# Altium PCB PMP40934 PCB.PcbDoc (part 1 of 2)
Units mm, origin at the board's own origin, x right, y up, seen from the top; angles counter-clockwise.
Board outline 30.1 x 65.43 mm, 4 copper layers (Component Side, Signal Layer 1, Signal Layer 2, Solder Side), stack 0.921 mm thick; 71 components, 34 nets, 202 pads, 421 vias.
Unrouted connection lines stored in the file: 46.
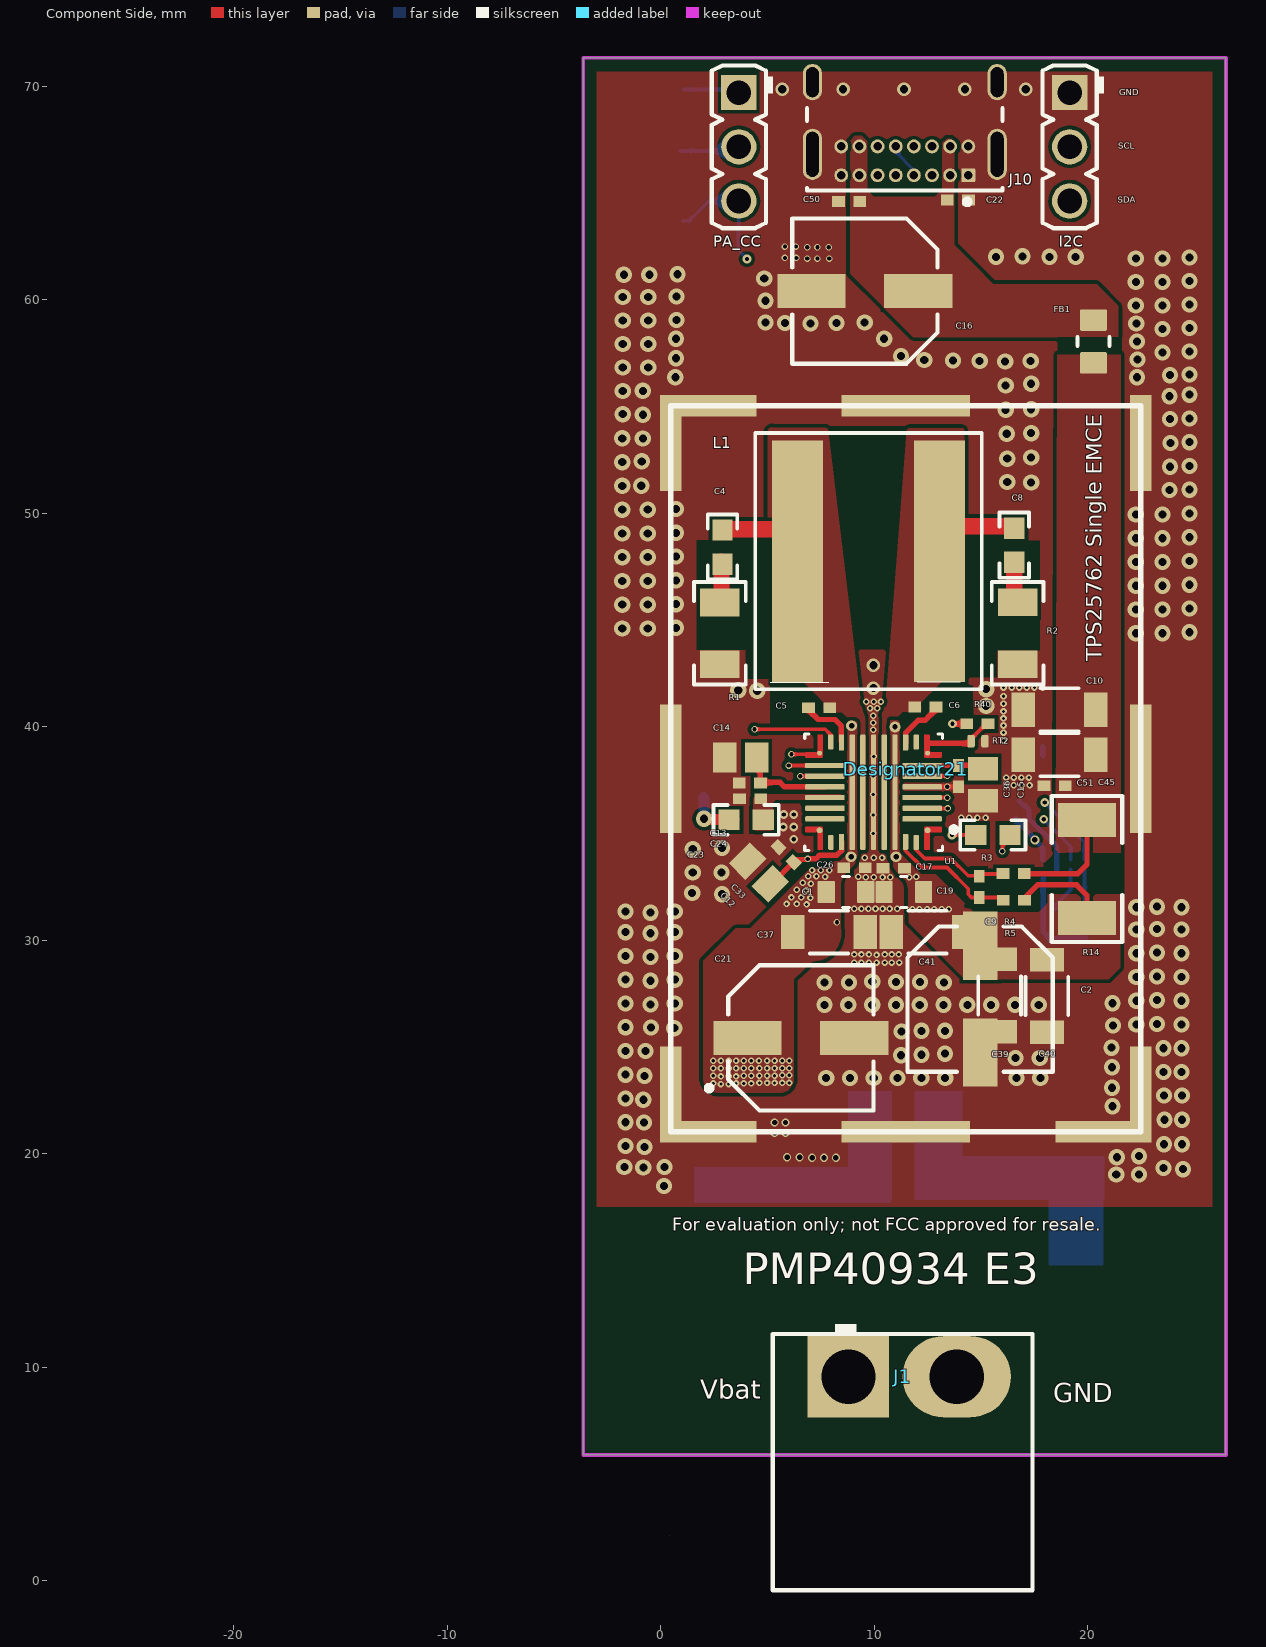
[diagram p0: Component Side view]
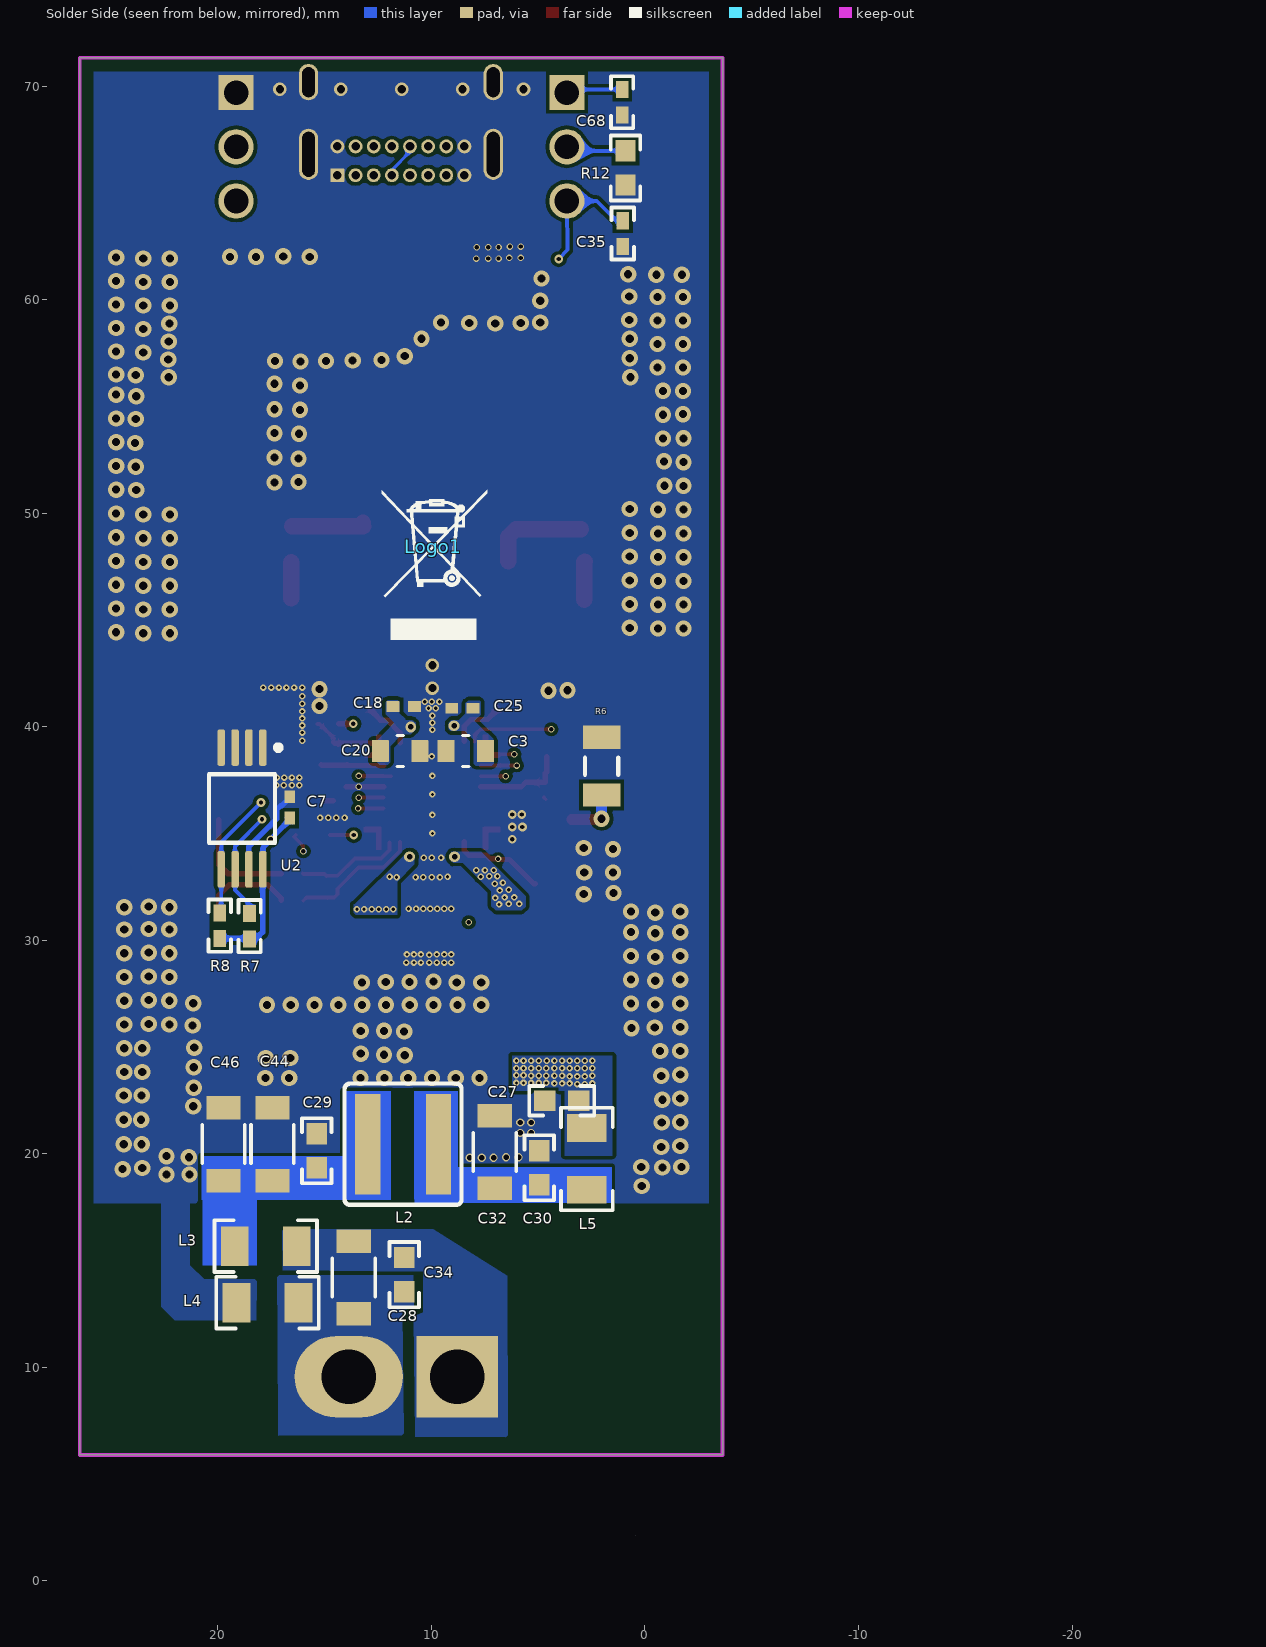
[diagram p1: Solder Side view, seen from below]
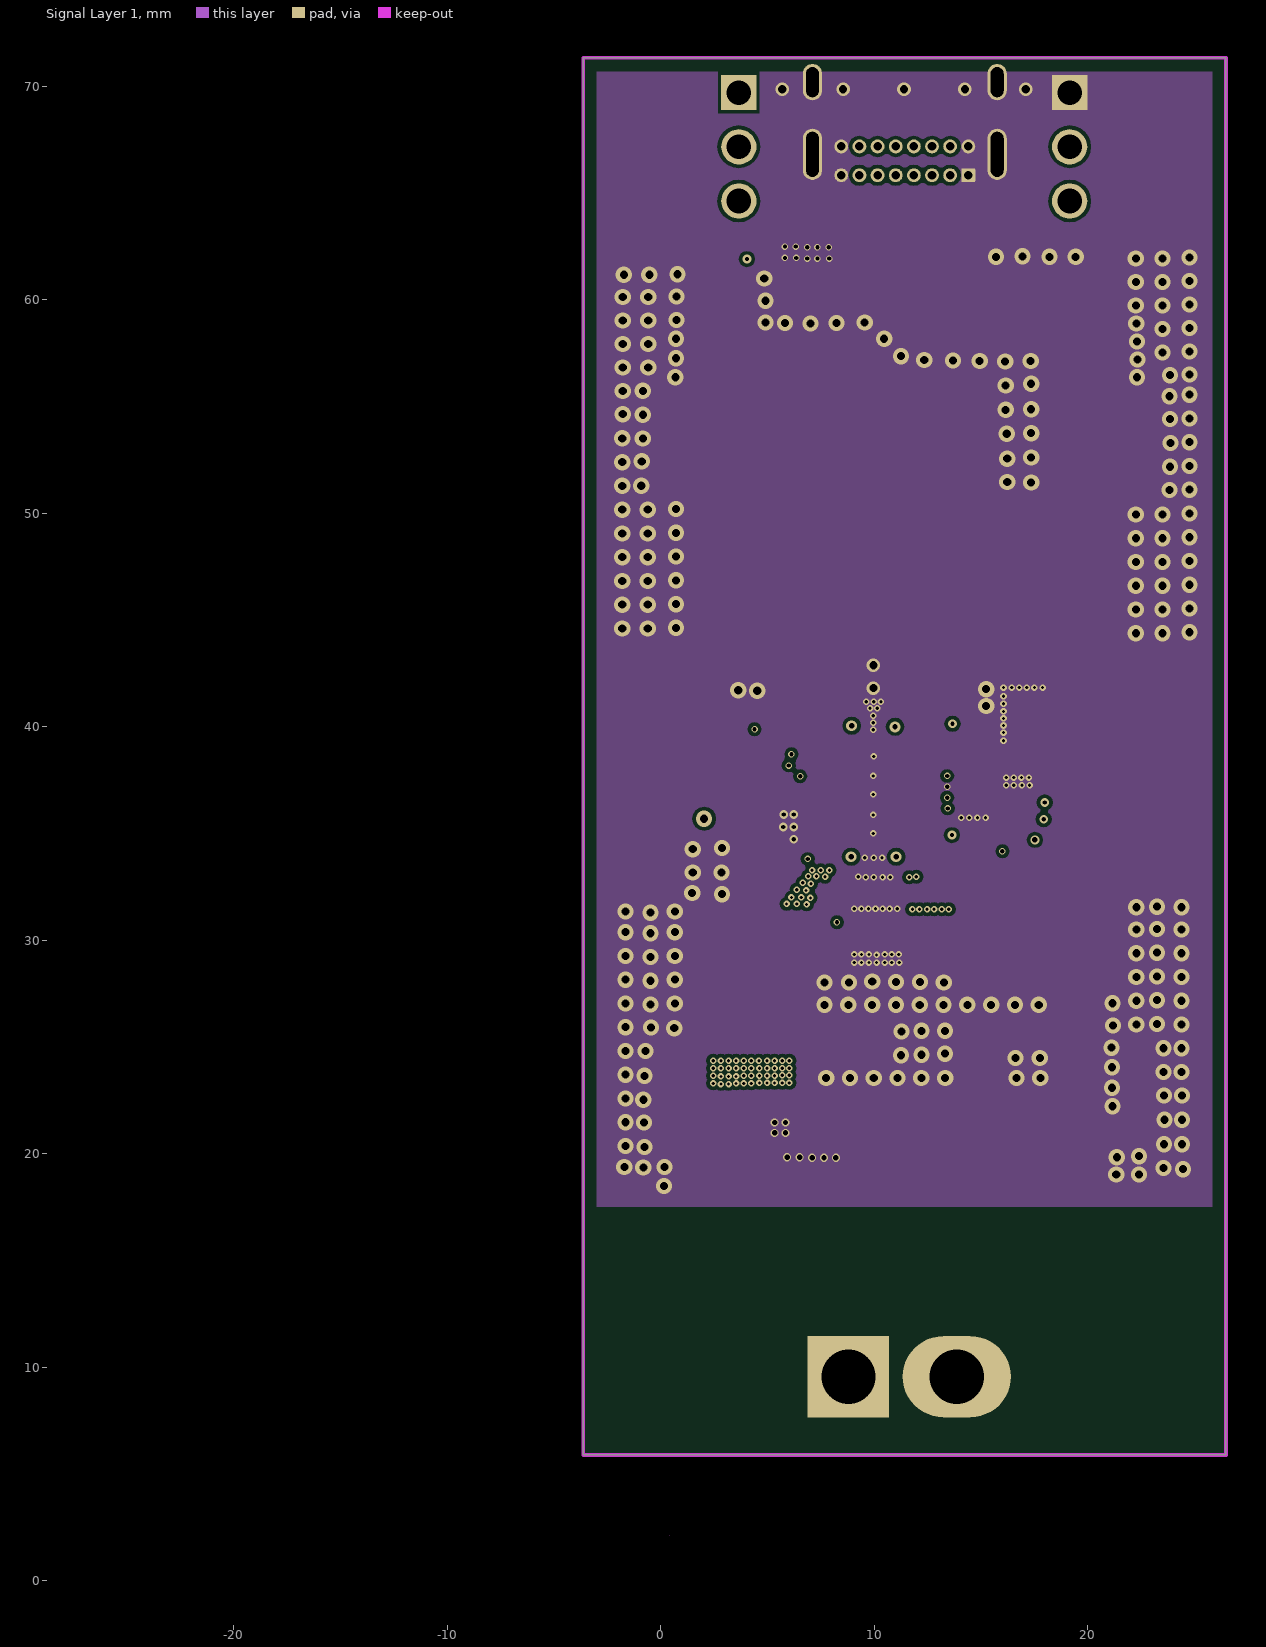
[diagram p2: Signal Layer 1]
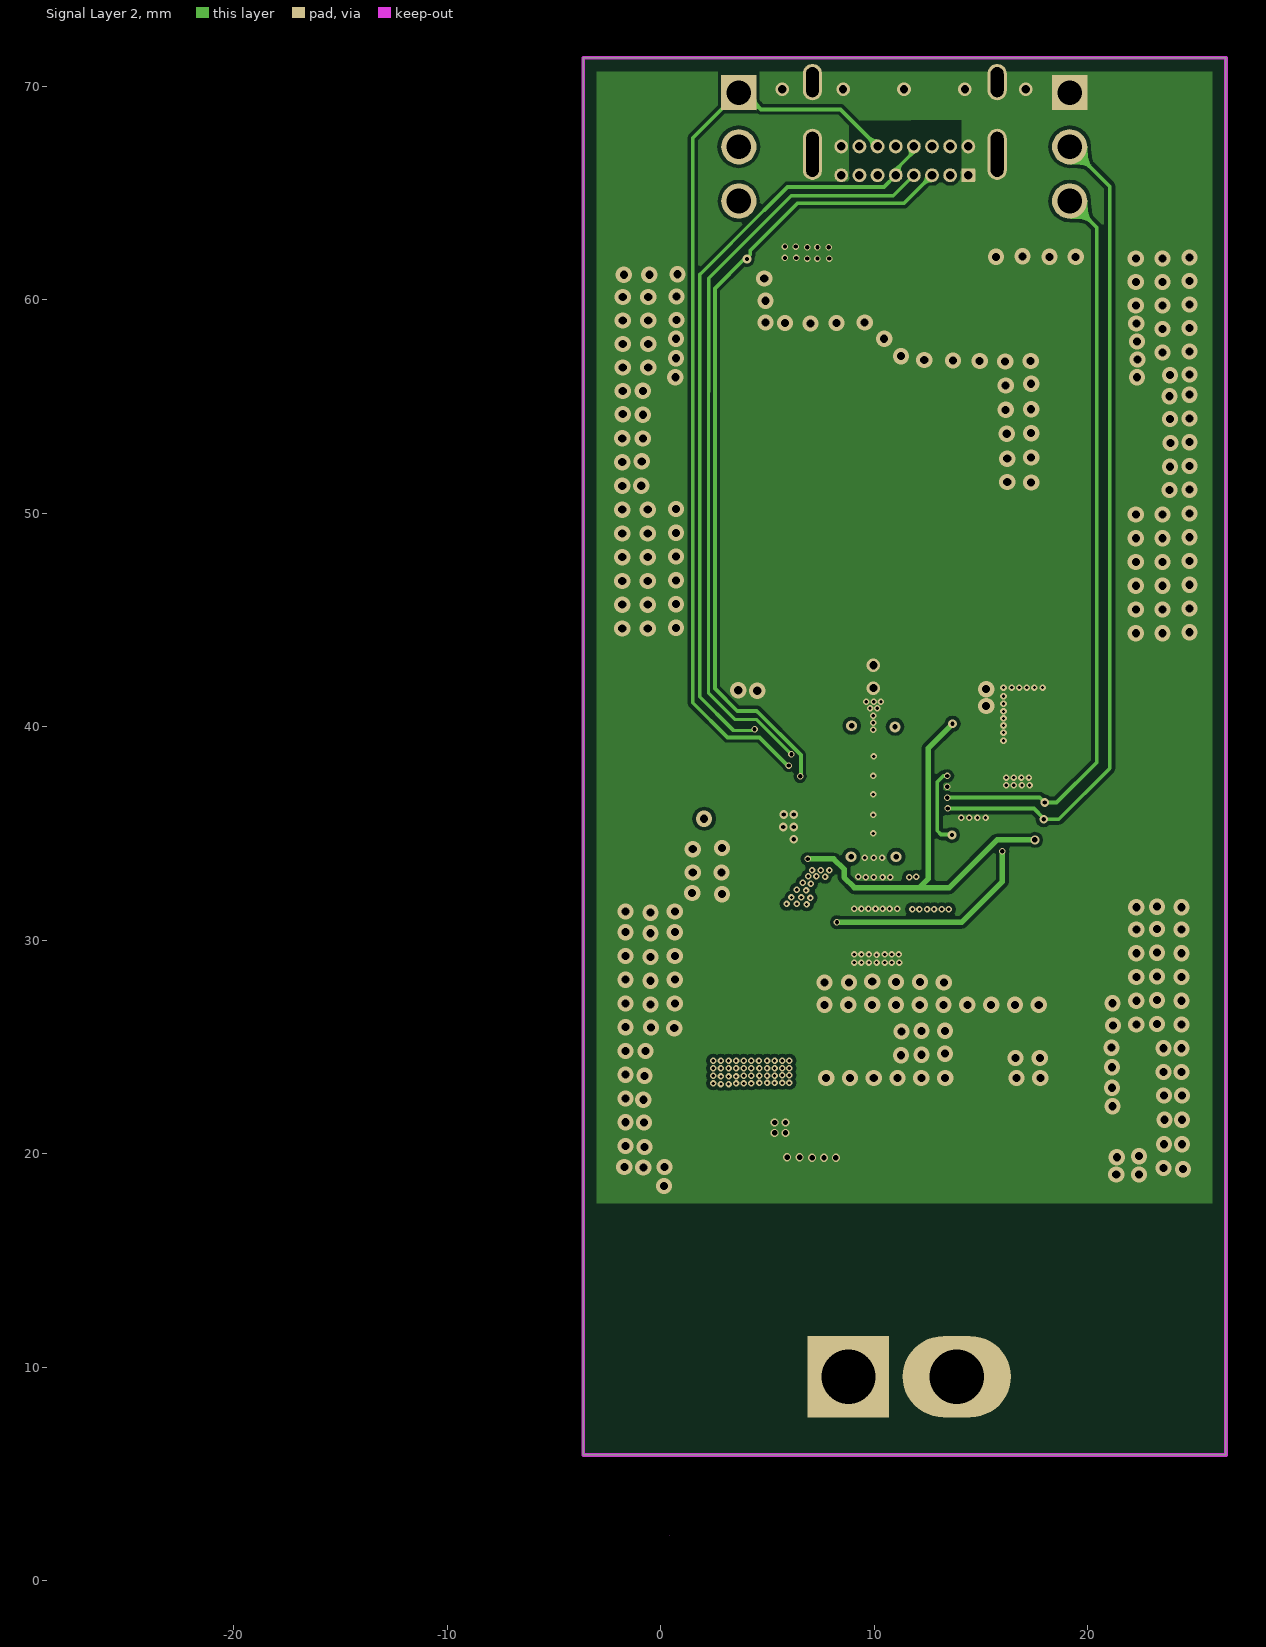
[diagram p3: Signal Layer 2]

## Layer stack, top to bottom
Top Solder: solder mask 0.0102, Solder Resist, Dk 3.5
Component Side: signal copper 0.072
Dielectric 1: core 0.254, FR-4, Dk 4.8
Signal Layer 1: signal copper 0.0711
Dielectric 3: prepreg 0.127, Dk 4.2
Signal Layer 2: signal copper 0.0711
Dielectric 4: core 0.254, FR-4, Dk 4.8
Solder Side: signal copper 0.072
Bottom Solder: solder mask 0.0102, Solder Resist, Dk 3.5

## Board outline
-3.632,5.893 -3.632,71.323 26.467,71.323 26.467,5.893
cut-out: 0.432,2.134

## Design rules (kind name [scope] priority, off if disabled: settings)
AcuteAngle [All] p1: minimum=4.50000000000000E+0001 checktracksonly=FALSE
AssemblyTestPointUsage [All] p1: valid=2
BoardOutlineClearance BoardOutlineClearance_MountingHoles [OnCopper and InComponentClass('Mounting Holes')] p1: gap=0.254 ignorepadtopadclearanceinfootprint=FALSE
BoardOutlineClearance BoardOutlineClearance_Poly [OnCopper and IsPoly] p2: gap=0.635 ignorepadtopadclearanceinfootprint=FALSE
BoardOutlineClearance [OnCopper and Not InComponentClass('Logo') and not InComponentClass('FiducialMark') and not InRegion(1000,500,4000,800) and not InPoly] p3: gap=0.254 ignorepadtopadclearanceinfootprint=FALSE
Clearance Clearance_Keepouts [((IsTrack Or IsArc) And Not InPoly) And IsFree and IsKeepOut vs ((IsTrack Or IsArc) And Not InPoly) And IsFree and IsKeepOut] p1: gap=0 ignorepadtopadclearanceinfootprint=FALSE
Clearance Clearance_Poly [InPolygon] p2: gap=0.165 ignorepadtopadclearanceinfootprint=FALSE except(0: Arc-Hole Track-Hole SMDPad-Hole THPad-Hole Via-Hole Fill-Hole Poly-Hole Region-Hole Text-Hole)
Clearance Clearance_FiducialMark [IsKeepOut and InComponentClass('FiducialMark') vs IsPad and InComponentClass('FiducialMark')] p3: gap=0 ignorepadtopadclearanceinfootprint=FALSE
Clearance [All] p4: gap=0 ignorepadtopadclearanceinfootprint=FALSE
ComponentClearance ComponentClearance_MountingHoles_FiducialMarks [InComponentClass('Mounting Holes') vs InComponentClass('FiducialMark')] p1: gap=0.127 collisioncheckmode=3 verticalgap=0.076 showdistances=FALSE
ComponentClearance ComponentClearance_Shunt [InComponentClass('Header') vs InComponentClass('Shunt')] p2: gap=0 collisioncheckmode=3 verticalgap=0 showdistances=FALSE
ComponentClearance ComponentClearance_Logo [InComponentClass('Logo')] p3: gap=1.27 collisioncheckmode=3 verticalgap=0.254 showdistances=FALSE
ComponentClearance ComponentClearance_ScrewToNut [(HasFootprint('NY PMS 440 0025 PH')) vs (HasFootprint('Keystone_1902C'))] p4: gap=0.127 collisioncheckmode=3 verticalgap=0.254 showdistances=FALSE
ComponentClearance ComponentClearance_MountingHoles [InComponentClass('Mounting Holes')] p5: gap=1.27 collisioncheckmode=3 verticalgap=2540 showdistances=FALSE
ComponentClearance ComponentClearance_SmallPassives [HasFootprint('0201*') or HasFootprint('0402*') or HasFootprint('0508') or HasFootprint('0603*') or HasFootprint('0612') or HasFootprint('0805*') or HasFootprint('0815*') or HasFootprint('0830*') or HasFootprint('1206*') or HasFootprint('1210*') or HasFootprint('1808*') or HasFootprint('1812*') or HasFootprint('1825*') or HasFootprint('2010*') or HasFootprint('2220*') or HasFootprint('2225*') or HasFootprint('2512*') or HasFootprint('2728*') or HasFootprint('3518*') vs HasFootprint('0201*') or HasFootprint('0402*') or HasFootprint('0508') or HasFootprint('0603*') or HasFootprint('0612') or HasFootprint('0805*') or HasFootprint('0815*') or HasFootprint('0830*') or HasFootprint('1206*') or HasFootprint('1210*') or HasFootprint('1808*') or HasFootprint('1812*') or HasFootprint('1825*') or HasFootprint('2010*') or HasFootprint('2220*') or HasFootprint('2225*') or HasFootprint('2512*') or HasFootprint('2728*') or HasFootprint('3518*')] p6: gap=0 collisioncheckmode=3 verticalgap=0 showdistances=FALSE
ComponentClearance ComponentClearance_THtoSMT [IsThruComponent vs IsSMTComponent] p7: gap=0.127 collisioncheckmode=3 verticalgap=0.127 showdistances=FALSE
ComponentClearance ComponentClearance_THtoTH [IsThruComponent vs IsThruComponent] p8: gap=0.127 collisioncheckmode=3 verticalgap=0.127 showdistances=FALSE
ComponentClearance [All] p9: gap=0 collisioncheckmode=3 verticalgap=0 showdistances=FALSE
DiffPairsRouting [All] p1: maxlimit=2.54 minlimit=0.152 mostfreqgap=0.254 toplayer_minwidth=0.152 toplayer_maxwidth=0.381 toplayer_prefwidth=0.381 midlayer1_minwidth=0.152 midlayer1_maxwidth=0.381 midlayer1_prefwidth=0.381 midlayer2_minwidth=0.152 midlayer2_maxwidth=0.381 midlayer2_prefwidth=0.381 bottomlayer_minwidth=0.152 bottomlayer_maxwidth=0.381 bottomlayer_prefwidth=0.381 maxuncoupledlength=25.4
FabricationTestPointUsage TestPointUsage [All] p1: valid=2 allowmultiple=FALSE
FabricationTestpoint Testpoint [All] p1: side=3 testpointundercomponent=TRUE minsize=1.016 maxsize=2.54 preferedsize=1.524 minholesize=0 maxholesize=1.016 preferedholesize=0.813 testpointgrid=0.025 allowsidetop=TRUE allowsidebottom=TRUE usegrid=TRUE gridtolerance=0
FanoutControl Fanout_LCC [IsLCC] p1: bgadir=Out bgaviamode=Centered fanoutstyle=Auto fanoutdirection=Alternating viagrid=0.025 // Fanout_LCC (Default Rule)
FanoutControl Fanout_BGA [IsBGA] p2: bgadir=Out bgaviamode=Centered fanoutstyle=Auto fanoutdirection=Alternating viagrid=0.025 // Fanout_BGA (Default Rule)
FanoutControl Fanout_Default [All] p4: bgadir=Out bgaviamode=Centered fanoutstyle=Auto fanoutdirection=Alternating viagrid=0.025 // Fanout_Default (Default Rule)
FanoutControl Fanout_Small [(CompPinCount < 5)] p5: bgadir=Out bgaviamode=Centered fanoutstyle=Auto fanoutdirection=OutThenIn viagrid=0.025 // Fanout_Small (Default Rule)
HoleSize [All] p1: absolutevalues=TRUE maxlimit=7.62 minlimit=0.127 maxpercent=80.000 minpercent=20.000
HoleToHoleClearance [All] p1: gap=0 allowstackedmicrovias=TRUE
MinimumAnnularRing MinimumAnnularRing_ThermalPadVias [IsVia and InAnyComponent] p1: minimumring=0.038
MinimumAnnularRing [All] p2: minimumring=0.038
MinimumSolderMaskSliver MinimumSolderMaskSliver_Logo [InComponentClass('Logo') vs InComponentClass('Logo')] p1: minsoldermaskwidth=0.018
MinimumSolderMaskSliver [All] p2: minsoldermaskwidth=0
PlaneConnect [All] p1: planeconnectstyle=Direct reliefexpansion=0.254 reliefentries=4 reliefconductorwidth=0.254 reliefairgap=0.254
PolygonConnect [All] p1: connectstyle=Direct reliefconductorwidth=0.254 reliefentries=4 polygonreliefangle="90 Angle" airgapwidth=0.254
RoutingVias ThermalPadVias [IsVia and InAnyComponent] p1: holewidth=1.27 width=1.27 viastyle="Through Hole" minholewidth=0.127 minwidth=0.254 maxholewidth=2.54 maxwidth=5.08
RoutingVias [All] p2: holewidth=0.254 width=0.406 viastyle="Through Hole" minholewidth=0.152 minwidth=0.254 maxholewidth=1.27 maxwidth=1.778
ShortCircuit [All vs InNet('No Net')] p1: allowed=FALSE
SilkToBoardRegionClearance [Not ((IsComment or IsDesignator) And (Hide <> 'False')) and not InRegion(1000,500,4000,800)] p1:
SilkToSilkClearance SilkToSilkClearance_Pb-FreeLogo [(HasFootprint('Pb-Free_Overlay_Medium') OR HasFootprint('Pb-Free_Overlay_Small')) vs (HasFootprint('Pb-Free_Overlay_Medium') OR HasFootprint('Pb-Free_Overlay_Small'))] p1: silktosilkclearance=0
SilkToSilkClearance [All] p2: silktosilkclearance=0
SilkToSolderMaskClearance SilkToComponentPadClearance [(IsPad or IsFill or IsRegion) and InAnycomponent] p1: minsilkscreentomaskgap=0 clearancetoexposedcopper=TRUE
SilkToSolderMaskClearance "Silk to Solder Mask Opening" [All] p2: minsilkscreentomaskgap=0 clearancetoexposedcopper=FALSE
SolderMaskExpansion [All] p1: expansion=0.05
Width [All] p1: maxlimit=2.54 minlimit=0.152 preferedwidth=0.254 checkconnectedcopper=TRUE
13 further rules are at their usual default settings.

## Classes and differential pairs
component class TPS25762: 3 C1 C2 C3 C4 C5 C6 C7 C8 C9 C10 C12 C13 C14 C15 C16 C17 C18 C19 C20 C21 C22 C23 C24 C25 C26 C33 C35 C36 C37 C39 C40 C41 C45 C50 C51 C68 FB1 I2C J10 L1 PA_CC R1 R2 R3 R4 R5 R6 R7 R8 R12 R14 R40 RT2 U1 U2
component class "Input filter": C27 C28 C29 C30 C32 C34 C44 C46 J1 L2 L3 L4 L5
component class Hardware: !PCB1 Logo1 Logo3
component class Header: I2C PA_CC
differential pair PA_D: +PA_D_P -PA_D_N

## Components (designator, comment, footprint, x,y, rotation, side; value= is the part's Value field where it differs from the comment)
C1 "GRT21BC71H475KE13L" FP-CGA4J1X7R1H475K125AC_0805-MFG 8.676,32.258 r180 top value=4.7µF
C2 "EEHZK1V101XP" Panasonic_D 14.961,27.243 r270 top value=100uF
C3 "GRT21BC71H475KE13L" FP-CGA4J1X7R1H475K125AC_0805-MFG 8.393,38.862 r180 bottom value=4.7µF
C4 "GRM188R72A332KA01D" 0603 2.896,48.412 r270 top value=3300pF
C5 "GRT155R71H104KE01D" 0402L 7.417,40.894 r0 top value=0.1uF
C6 "GRT155R71H104KE01D" 0402L 12.395,40.919 r180 top value=0.1uF
C7 "GRT155R71H104KE01D" 0402L 16.637,36.22 r270 bottom value=0.1uF
C8 "GRM188R72A332KA01D" 0603 16.561,48.501 r270 top value=3300pF
C9 "CGA3E2X7R1H104K080AA" 0402L 14.91,32.495 r90 top value=0.22uF
C10 "GRT31CD71H106KE13L" 1206_190 18.667,40.792 r180 top value=10uF
C12 "GCM21BR71C475KA73K" 0805L 4.6,33.169 r135 top value=4.7uF
C13 "GRT155R71H104KE01D" 0402L 4.174,37.363 r180 top value=0.1uF
C14 "GCM21BR71C475KA73K" 0805L 3.746,38.557 r180 top value=4.7uF
C15 "GCM21BR71C475KA73K" 0805L 15.088,37.274 r270 top value=4.7uF
C16 "EEHZK1V101XP" Panasonic_D 9.565,60.401 r180 top value=100uF
C17 "GRT155R71H104KE01D" 0402L 10.914,33.376 r0 top value=0.1uF
C18 "GRT155R71H104KE01D" 0402L 11.295,40.945 r0 bottom value=0.1uF
C19 "GRT21BC71H475KE13L" FP-CGA4J1X7R1H475K125AC_0805-MFG 11.39,32.258 r0 top value=4.7µF
C20 "GRT21BC71H475KE13L" FP-CGA4J1X7R1H475K125AC_0805-MFG 11.466,38.862 r0 bottom value=4.7µF
C21 "EEHZK1V101XP" Panasonic_D 6.561,25.425 r0 top value=100uF
C22 "GRT155R71H104KE01D" 0402L 13.919,64.668 r180 top value=0.1uF
C23 "CGA3E3X7R1H474K080AE" 0603 4.001,35.636 r180 top value=0.47uF
C24 "GRT155R71H104KE01D" 0402L 4.183,36.627 r180 top value=0.1uF
C25 "GRT155R71H104KE01D" 0402L 8.552,40.869 r180 bottom value=0.1uF
C26 "GRT155R71H104KE01D" 0402L 9.076,33.401 r180 top value=0.1uF
C27 "GCM1887U2A392JA16D" 0603 3.899,22.479 r0 bottom value=3900pF
C28 "GRT31CD71H106KE13L" 1206_190 13.64,14.2 r270 bottom value=10uF
C29 "GCM1887U2A392JA16D" 0603 15.367,20.142 r90 bottom value=3900pF
C30 "GCM1887U2A392JA16D" 0603 4.953,19.342 r90 bottom value=3900pF
C32 "GRT31CD71H106KE13L" 1206_190 7.036,20.091 r90 bottom value=10uF
C33 "GRT155R71H104KE01D" 0402L 5.869,34.009 r135 top value=0.1uF
C34 "GCM1887U2A392JA16D" 0603 11.278,14.34 r270 bottom value=3900pF
C35 "GRM155R71H331KA01D" 0402 1.041,63.094 r270 bottom value=330pF
C36 "GRT155R71H104KE01D" 0402L 13.945,37.686 r270 top value=0.1uF
C37 "GRT31CD71H106KE13L" 1206_190 7.873,30.378 r0 top value=10uF
C39 "GRT31CD71H106KE13L" 1206_190 15.875,27.408 r270 top value=10uF
C40 "GRT31CD71H106KE13L" 1206_190 18.085,27.383 r270 top value=10uF
C41 "GRT31CD71H106KE13L" 1206_190 12.495,30.378 r180 top value=10uF
C44 "GRT31CD71H106KE13L" 1206_190 17.45,20.447 r90 bottom value=10uF
C45 "GRT31CD71H106KE13L" 1206_190 18.671,38.684 r180 top value=10uF
C46 "GRT31CD71H106KE13L" 1206_190 19.736,20.447 r90 bottom value=10uF
C50 "GRT155R71H104KE01D" 0402L 8.822,64.592 r0 top value=0.1uF
C51 "GRT155R71H104KE01D" 0402L 18.448,37.236 r0 top value=0.1uF
C68 "GRM155R71H331KA01D" 0402 1.067,69.24 r270 bottom value=330pF
Designator21 "Comment" "Shield 19.7mm X 19.7mm" 0.476,21.031 r0 top
FB1 "BLM21SP700SZ1D" 0805_HV1 20.269,58.039 r90 top
I2C "61300311121" WURTH_61300311121 19.152,67.158 r270 top
J1 "1757242" PHOENIX_1757242 11.328,5.563 r0 top
J10 "USB4085-GF-A" FP-USB4085-GF-A_PTH_USB-C-MFG 11.43,69.85 r180 top
L1 "XAL1010-472MEB" XAL1010 9.728,47.752 r0 top value=4.7uH
L2 "XFL5030-472MEC" XFL5030 11.328,20.447 r180 bottom value=4.7uH
L3 "BLM31SN500SZ1L" 1206 17.757,15.672 r0 bottom value="50 ohm"
L4 "BLM31SN500SZ1L" 1206 17.681,13.03 r0 bottom value="50 ohm"
L5 "BLM31SN500SZ1L" 1206 2.718,19.759 r90 bottom value="50 ohm"
Logo1 "WEEE logo" WEEE_Minimum 9.906,48.438 r180 bottom
Logo3 "FCC disclaimer" FCC_disclaimer 32.233,20.828 r90 top
PA_CC "61300311121" WURTH_61300311121 3.658,67.158 r270 top
R1 "ERJ-8RQF2R2V" 1206 2.769,44.372 r90 top value=2.20
R2 "CRCW12061R00FKEA" 1206 16.713,44.376 r90 top value=1.00
R3 "CRCW060347K0FKEA" 0603 15.554,34.925 r0 top value=47.0k
R4 "RMCF0603ZT0R00" 0402L 16.527,33.122 r0 top value=0
R5 "RMCF0603ZT0R00" 0402L 16.543,31.877 r0 top value=10.0
R6 "RC1206FR-0710RL" 1206L 2.032,38.151 r270 bottom value=10.0
R7 "RK73H1ETTP3301F" 0402 18.517,30.658 r270 bottom value=3.30k
R8 "RK73H1ETTP3301F" 0402 19.914,30.683 r270 bottom value=3.30k
R12 "CRCW06035K10JNEA" 0603 0.914,66.167 r90 bottom value=5.1k
R14 "WSL2010R0100FEA18" 2010 19.964,33.336 r270 top value=0.01
R40 "ERJ-2GEJ103X" 0402L 14.834,40.132 r180 top value=10k
RT2 "TMP6131DECR" DEC0002A 14.859,39.319 r180 top
U1 "TPS25772RQLRQ1" RQL0029A-MFG 9.968,36.932 r180 top
U2 "24LC256-I/ST" TSSOP-8 18.872,36.17 r270 bottom

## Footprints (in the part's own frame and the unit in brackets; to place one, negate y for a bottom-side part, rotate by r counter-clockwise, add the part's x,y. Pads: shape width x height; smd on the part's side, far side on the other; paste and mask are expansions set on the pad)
0402 [mm] "0402 from SM-752 data"
  rect 0.8x0.6 smd: 1(-0.6,0) 2(0.6,0)
  silkscreen extent -1.22,-0.52 1.22,0.52, body extent -0.55,-0.3 0.55,0.3, height 0.6
0402L [mm] "0402 from SM-752 data"
  rect 0.6x0.5 smd: 1(-0.5,0) 2(0.5,0)
  body extent -0.55,-0.3 0.55,0.3, height 0.6
0603 [mm] "0603 from SM-752 data"
  rect 1x0.95 smd: 1(-0.8,0) 2(0.8,0)
  silkscreen extent -1.52,-0.69 1.52,0.69, body extent -0.87,-0.47 0.87,0.47, height 1
0805_HV1 [mm]
  rrect10% 1x1.25 smd: 1(-1,0) 2(1,0)
  silkscreen extent -0.2,-0.75 0.2,0.75, body extent -1.35,-0.82 1.35,0.82, height 0.25
0805L [mm] "0805 from SM-752 data"
  rect 1.1x1.4 smd: 1(-0.75,0) 2(0.75,0)
  body extent -1.1,-0.72 1.1,0.72, height 1.45
1206 [mm] "1206 from SM-752 data"
  rect 1.3x1.85 smd: 1(-1.45,0) 2(1.45,0)
  silkscreen extent -2.4,-1.21 2.4,1.21, body extent -1.7,-0.9 1.7,0.9, height 1.35
1206_190 [mm] "1206_190"
  rect 1.1x1.6 smd: 1(-1.7,0) 2(1.7,0)
  silkscreen extent -0.9,-1 0.9,1, body extent -1.75,-0.95 1.75,0.95, height 1.9
1206L [mm] "1206 from SM-752 data"
  rect 1.1x1.75 smd: 1(-1.35,0) 2(1.35,0)
  silkscreen extent -0.4,-0.77 0.4,0.77, body extent -1.7,-0.9 1.7,0.9, height 1.35
2010 [mm] "Chip Capacitor, Body 5.08x2.54mm, IPC Medium Density"
  rect 1.6x2.7 smd: 1(-2.3,0) 2(2.3,0)
  silkscreen extent -3.42,-1.65 3.42,1.65, body extent -2.73,-1.45 2.73,1.45, height 1.66
DEC0002A [mm] "X1SON-2"
  rrect57% 0.35x0.6 smd paste-0.5 mask-0.05: 1(-0.325,0) 2(0.325,0)
  rrect33% 0.3x0.5 on Top Paste: 1S(-0.35,0) 2S(0.35,0)
  body extent -0.5,-0.3 0.5,0.3, height 0.5
FCC_disclaimer [mm]
FP-CGA4J1X7R1H475K125AC_0805-MFG [mm]
  rrect13% 0.8x1.05 smd paste+0 mask+0: 1(-0.925,0) 2(0.925,0)
  silkscreen extent -0.15,-0.73 0.15,0.73, body extent -1,-0.62 1,0.63, height 1.45
FP-USB4085-GF-A_PTH_USB-C-MFG [mm]
  rrect100% 0.9x2.4 hole 2.1 slot 0.6 at 0 deg paste-1000 mask+0: 1(-4.325,3.045) 2(4.325,3.045)
  rrect100% 0.9x1.7 hole 1.4 slot 0.6 at 0 deg paste-1000 mask+0: 3(-4.325,-0.335) 4(4.325,-0.335)
  rrect15% 0.65x0.65 hole 0.4 paste-1000 mask+0: A1(-2.975,4.025)
  round 0.65 hole 0.4 paste-1000 mask+0: A4(-2.125,4.025) A5(-1.275,4.025) A6(-0.425,4.025) A7(0.425,4.025) A8(1.275,4.025) A9(2.125,4.025) A12(2.975,4.025) B1(2.975,2.675) B4(2.125,2.675) B5(1.275,2.675) B6(0.425,2.675) B7(-0.425,2.675) B8(-1.275,2.675) B9(-2.125,2.675) B12(-2.975,2.675)
  silkscreen extent -4.57,0.89 4.57,5.39, body extent -4.87,-4.83 4.87,4.83, height 0.25
Panasonic_D [mm] "SMD, 2-Leads, Dia 6.3mm"
  rect 3.2x1.6 smd: 1(-2.5,0) 2(2.5,0)
  silkscreen extent -3.4,-3.4 3.4,3.4, body extent -3.4,-3.4 3.4,3.4, height 6.11
PHOENIX_1757242 [mm] "Header, 5.08 mm, 2x1, R/A, TH"
  rect 3.81x3.81 hole 2.54: 1(-2.54,4)
  oval 5.08x3.81 hole 2.54: 2(2.54,4)
  silkscreen extent -6.08,-6 6.08,6.47, body extent -6.06,-6.02 6.1,5.98, height 8.6
RQL0029A-MFG [mm]
  round 0.278 smd paste+0 mask+0: 1(-2.53,1.78) 25(2.53,1.78)
  rrect40% 1.85x0.25 smd paste-1000 mask+0: 2(-2.275,1.25) 3(-2.275,0.75) 4(-2.275,0.25) 5(-2.275,-0.25) 6(-2.275,-0.75) 7(-2.275,-1.25) 19(2.275,-1.25) 20(2.275,-0.75) 21(2.275,-0.25) 22(2.275,0.25) 23(2.275,0.75) 24(2.275,1.25)
  round 0.229 smd paste+0 mask+0: 8(-2.53,-1.823) 18(2.53,-1.823)
  rrect40% 0.25x0.7 smd paste+0 mask+0: 9(-2,-2.35) 17(2,-2.35) 26(2,2.35) 29(-2,2.35)
  rrect40% 0.25x0.75 smd paste+0 mask+0: 10(-1.5,-2.325) 16(1.5,-2.325) 27(1.5,2.325) 28(-1.5,2.325)
  rrect40% 0.25x5.4 smd paste-1000 mask+0: 11(-1,0) 12(-0.5,0) 13(0,0) 14(0.5,0) 15(1,0)
  Component Side region: -2.425,-2.7 -2.575,-2.7 -2.594,-2.696 -2.61,-2.685 -2.621,-2.669 -2.625,-2.65 -2.625,-2.65 -2.625,-1.925 -2.629,-1.906 -2.64,-1.89 -2.656,-1.879 -2.675,-1.875 -2.675,-1.875 -3.15,-1.875 -3.175,-1.868 -3.193,-1.85 -3.2,-1.825 -3.2,-1.825 -3.2,-1.675 -3.196,-1.656 -3.185,-1.64 -3.169,-1.629 -3.15,-1.625 -3.15,-1.625 -2.425,-1.625 -2.406,-1.629 -2.39,-1.64 -2.379,-1.656 -2.375,-1.675 -2.375,-1.675 -2.375,-2.65 -2.379,-2.669 -2.39,-2.685 -2.406,-2.696 -2.425,-2.7
  Component Side region: 2.425,-2.7 2.575,-2.7 2.594,-2.696 2.61,-2.685 2.621,-2.669 2.625,-2.65 2.625,-2.65 2.625,-1.925 2.629,-1.906 2.64,-1.89 2.656,-1.879 2.675,-1.875 2.675,-1.875 3.15,-1.875 3.175,-1.868 3.193,-1.85 3.2,-1.825 3.2,-1.825 3.2,-1.675 3.196,-1.656 3.185,-1.64 3.169,-1.629 3.15,-1.625 3.15,-1.625 2.425,-1.625 2.406,-1.629 2.39,-1.64 2.379,-1.656 2.375,-1.675 2.375,-1.675 2.375,-2.65 2.379,-2.669 2.39,-2.685 2.406,-2.696 2.425,-2.7
  Component Side region: 2.425,2.7 2.575,2.7 2.594,2.696 2.61,2.685 2.621,2.669 2.625,2.65 2.625,2.65 2.625,1.925 2.629,1.906 2.64,1.89 2.656,1.879 2.675,1.875 2.675,1.875 3.15,1.875 3.175,1.868 3.193,1.85 3.2,1.825 3.2,1.825 3.2,1.675 3.196,1.656 3.185,1.64 3.169,1.629 3.15,1.625 3.15,1.625 2.425,1.625 2.406,1.629 2.39,1.64 2.379,1.656 2.375,1.675 2.375,1.675 2.375,2.65 2.379,2.669 2.39,2.685 2.406,2.696 2.425,2.7
  Component Side region: -2.425,2.7 -2.575,2.7 -2.594,2.696 -2.61,2.685 -2.621,2.669 -2.625,2.65 -2.625,2.65 -2.625,1.925 -2.629,1.906 -2.64,1.89 -2.656,1.879 -2.675,1.875 -2.675,1.875 -3.15,1.875 -3.169,1.871 -3.185,1.86 -3.196,1.844 -3.2,1.825 -3.2,1.825 -3.2,1.675 -3.196,1.656 -3.185,1.64 -3.169,1.629 -3.15,1.625 -3.15,1.625 -2.425,1.625 -2.406,1.629 -2.39,1.64 -2.379,1.656 -2.375,1.675 -2.375,1.675 -2.375,2.65 -2.379,2.669 -2.39,2.685 -2.406,2.696 -2.425,2.7
  silkscreen extent -3.88,-2.73 3.22,2.73, body extent -3.3,-2.8 3.3,2.8, height 0.25
"Shield 19.7mm X 19.7mm" [mm]
  rect 1x4.5 smd: 0(0,1.75) 0(0,32.25) 0(22,1.75) 0(22,32.25)
  rect 1x6 smd: 0(0,17) 0(22,17)
  rect 4.5x1 smd: 0(1.75,0) 0(1.75,34) 0(20.25,0)
  rect 6x1 smd: 0(11,0) 0(11,34)
  silkscreen extent 0,0 22,34
TSSOP-8 [mm] "TSSOP, 8-Leads, Body 3.1x4.5mm (max), Pitch 0.65mm, IPC Medium Density"
  rrect50% 1.7x0.35 smd: 1(-2.85,0.975) 2(-2.85,0.325) 3(-2.85,-0.325) 4(-2.85,-0.975) 5(2.85,-0.975) 6(2.85,-0.325) 7(2.85,0.325) 8(2.85,0.975)
  silkscreen extent -2.97,-1.55 1.6,1.82, body extent -3.2,-1.55 3.2,1.55, height 1.07
WEEE_Minimum [mm] "WEEElie bin"
  silkscreen extent -2.42,-4.38 2.52,2.65
WURTH_61300311121 [mm] "Header, 2.54mm, 3x1, TH"
  rect 1.65x1.65 hole 1.15: 1(-2.54,0)
  round 1.65 hole 1.15: 2(0,0) 3(2.54,0)
  silkscreen extent -3.81,-1.27 3.81,1.6, body extent -3.81,-1.27 3.81,1.27, height 8.54
XAL1010 [mm] "COILCRAFT"
  rect 2.38x11.31 smd: 1(-3.325,0) 2(3.325,0)
  silkscreen extent -5.3,-6 5.3,6, body extent -5.25,-5.9 5.25,5.9, height 10
XFL5030 [mm] "SMD, 2-Leads, Body 5.48x5.28mm"
  rect 1.18x4.7 smd: 1(-1.655,0) 2(1.655,0)
  silkscreen extent -2.74,-2.84 2.74,2.84, body extent -2.74,-2.84 2.74,2.84, height 3.1

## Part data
C1: library part CMP-0090082-1, "Cap Ceramic 4.7uF 50V X7R 10% Pad SMD 0805 +125°C Automotive T/R", Manufacturer="TDK Corporation", Operating Temperature Range="-55°C to +125°C", TempCo=15%, Temperature Characteristic=X7R, Tolerance_%=0.1%, ValueDisplayed=4.7uF
C2 C16 C21: library part CMP-0010737-1, "CAP, AL, 100 uF, 35 V, +/- 20%, 0.26 ohm, AEC-Q200 Grade 2, SMD", Cap_Case=6.3x5.8mm, Manufacturer=Panasonic, PartNumber=EEE-FT1V101AP, Supplier Part Number 1=PCE5016CT-ND, Tolerance_%=20%, Value1="0.26 ohm", Value2=35V, ValueDisplayed=100uF
C3: library part CMP-0090082-1, "Cap Ceramic 4.7uF 50V X7R 10% Pad SMD 0805 +125°C Automotive T/R", Manufacturer="TDK Corporation", Operating Temperature Range="-55°C to +125°C", PartNumber=CGA4J1X7R1H475K125AC, TempCo=15%, Temperature Characteristic=X7R, Tolerance_%=0.1%, ValueDisplayed=4.7uF
C4 C8: library part CMP-0007479-3, "CAP, CERM, 3300 pF, 100 V, +/- 10%, X7R, 0603", Cap_Case=0603, Manufacturer=MuRata, Supplier Part Number 1=490-1481-1-ND, TempCo=X7R, Tolerance_%=10%, Value1=Unknown, Value2=100V, ValueDisplayed=3300pF
C5 C6 C7: library part CMP-0006325-2, "CAP, CERM, 0.1 uF, 50 V, +/- 10%, X7R, AEC-Q200 Grade 1, 0402", Cap_Case=0402, Manufacturer=TDK, PartNumber=CGA2B3X7R1H104K050BB, Supplier Part Number 1=445-6899-1-ND, TempCo=X7R, Tolerance_%=10%, Value1="0.039064 ohm", Value2=50V, ValueDisplayed=0.1uF
C9: library part CMP-0006325-2, "CAP, CERM, 0.22 uF, 35 V, +/- 10%, X7R, AEC-Q200 Grade 1, 0402", Cap_Case=0402, Manufacturer=TDK, PartNumber=CGA2B1X7R1V224K050BC, Supplier Part Number 1=445-6899-1-ND, TempCo=X7R, Tolerance_%=10%, Value1="0.039064 ohm", Value2=50V, ValueDisplayed=0.22uF
C10 C28 C32 C37 C39 C40 C41 C44 C45 C46: library part CMP-0008808-1, "CAP, CERM, 10 µF, 50 V,+/- 10%, X7R, AEC-Q200 Grade 1, 1206", Cap_Case=1206, Manufacturer=MuRata, PartNumber=GRT31CD71H106KE13, TempCo=X7T, Tolerance_%=10%, Value1=Unknown, Value2=50V, ValueDisplayed=10uF
C12 C14 C15: library part CMP-0084739-1, "CAP, CERM, 4.7 µF, 10 V,+/- 10%, X7R, AEC-Q200 Grade 1, 0805", Cap_Case=0805, Manufacturer=TDK, PartNumber=CGA4J1X7R1H475K125AC, TempCo=X7R, Tolerance_%=10%, Value2=10V, ValueDisplayed=4.7µF
C13 C33 C36: library part CMP-0006201-2, "CAP, CERM, 0.1 uF, 16 V, +/- 10%, X7R, 0402", Cap_Case=0402, Manufacturer=AVX, PartNumber=0402YC104KAT2A, Supplier Part Number 1=478-7888-1-ND, TempCo=X7R, Tolerance_%=10%, Value1=Unknown, Value2=16V, ValueDisplayed=0.1uF
C17 C18 C22 C24 C25 C26 C50 C51: library part CMP-0006325-2, "CAP, CERM, 0.1 uF, 50 V, +/- 10%, X7R, AEC-Q200 Grade 1, 0402", Cap_Case=0402, Manufacturer=Murata, PartNumber=GRT155R71H104KE01, Supplier Part Number 1=445-6899-1-ND, TempCo=X7R, Tolerance_%=10%, Value1="0.039064 ohm", Value2=50V, ValueDisplayed=0.1uF
C19 C20: library part CMP-0090082-1, "Cap Ceramic 4.7uF 50V X7R 10% Pad SMD 0805 +125°C Automotive T/R", Manufacturer="TDK Corporation", Operating Temperature Range="-55°C to +125°C", Part Number=CGA4J1X7R1H475K125AC, TempCo=15%, Temperature Characteristic=X7R, Tolerance_%=0.1%, ValueDisplayed=4.7uF
C23: library part CMP-0007097-2, "CAP, CERM, 0.47 uF, 50 V, +/- 10%, X7R, AEC-Q200 Grade 1, 0603", Cap_Case=0603, Manufacturer=TDK, Supplier Part Number 1=445-172475-1-ND, TempCo=X7R, Tolerance_%=10%, Value1=Unknown, Value2=50V, ValueDisplayed=0.47uF
C27 C29 C30 C34: library part CMP-0007481-1, "CAP, CERM, 3900 pF, 100 V, +/- 10%, X7R, 0603", Cap_Case=0603, Manufacturer=MuRata, PartNumber=GRM188R72A392KA01D, Supplier Part Number 1=GRM188R72A392KA01D-ND, TempCo=X7R, Tolerance_%=10%, Value1=Unknown, Value2=100V, ValueDisplayed=3900pF
C35 C68: library part CMP-0006687-2, "CAP, CERM, 330 pF, 50 V, +/- 10%, X7R, 0402", Cap_Case=0402, Manufacturer=MuRata, Supplier Part Number 1=490-3247-1-ND, TempCo=X7R, Tolerance_%=10%, Value1=Unknown, Value2=50V, ValueDisplayed=330pF
FB1: library part CMP-0091807-2, "Chip Ferrite Bead, 0805, 110O @ 100MHz, 0.013O, 25%, 5A", Impedance At Frequency="110O @ 100MHz", Manufacturer=Murata, Operating Temperature Range="-55°C to +150°C", Part Number=BLM21SP111BH1D, Test Frequency=100MHz, Tolerance_%=0.25%
I2C PA_CC: library part CMP-0054796-1, "Header, 2.54 mm, 3x1, Gold, TH", Manufacturer="Wurth Elektronik", Supplier Part Number 1=732-5316-ND
J1: library part CMP-0055534-1, "Header (Shrouded), 5.08 mm, 2x1, Tin, R/A, TH", Manufacturer="Phoenix Contact", Supplier Part Number 1=277-1106-ND
J10: library part CMP-0087858-1, "USB - C (Type - C) USB 2.0 Receptacle Connector 16 Position Through Hole, Right Angle", Current_A=4.25A, Manufacturer="Global Connector Technology", Voltage_V=20V
L1: library part CMP-0060950-1, "Inductor, Shielded, Composite, 4.7 uH, 24 A, 0.01 ohm, SMD", Manufacturer=Coilcraft, Supplier Part Number 1=994-XAL1010-472MEB, Value1="0.01 ohm", Value2=24A, ValueDisplayed=4.7uH
L2: library part CMP-0076756-1, "Inductor, Shielded, Composite, 4.7 µH, 2.5 A, 0.022 ohm, AEC-Q200 Grade 1, SMD", Manufacturer=Coilcraft, Value1="0.022 ohm", Value2=2.5A, ValueDisplayed=4.7µH
L3 L4 L5: library part CMP-0003367-1, "Ferrite Bead, 50 ohm @ 100 MHz, 12 A, 1206", Manufacturer=MuRata, Supplier Part Number 1=490-13269-1-ND, Value1="0.0016 ohm", Value2=12A, ValueDisplayed="50 ohm"
Logo1: library part CMP-0074769-1
Logo3: library part CMP-0074847-1, "FCC_disclaimer"
R1: library part CMP-0017777-3, "RES, 2.20, 1%, 0.25 W, AEC-Q200 Grade 0, 1206", Manufacturer=Panasonic, Power_W=250mW, Supplier Part Number 1=P2.2RCT-ND, TempCo="200 ppm/C", Tolerance_%=1%, Value2=0.25W, Value_Code=2R20, ValueDisplayed=2.20
R2: library part CMP-0016745-3, "RES, 1.00, 1%, 0.25 W, AEC-Q200 Grade 0, 1206", Manufacturer=Vishay-Dale, Power_W=250mW, Supplier Part Number 1=53K1855, TempCo="100 ppm/C", Tolerance_%=1%, Value2=0.25W, Value_Code=1R00, ValueDisplayed=1.00
R3: library part CMP-0022438-1, "RES, 47.0 k, 1%, 0.1 W, AEC-Q200 Grade 0, 0603", Manufacturer=Vishay-Dale, Power_W=100mW, Supplier Part Number 1=541-47.0KHCT-ND, TempCo="100 ppm/C", Tolerance_%=1%, Value2=0.1W, Value_Code=47k0, ValueDisplayed=47.0k
R4: library part CMP-0081856-1, "RES, 0, 0%, 0.2 W, AEC-Q200 Grade 0, 0402", Manufacturer=Vishay-Dale, PartNumber=CRCW04020000Z0EDHP, Power_W=200mW, Supplier Part Number 1=541-0.0YBTR-ND, Tolerance_%=0%, Value2=0.2W, Value_Code=0
R5: library part CMP-0025963-2, "RES, 10.0, 1%, 0.063 W, 0402", Manufacturer=Vishay-Dale, PartNumber=CRCW040210R0FKED, Power_W=63mW, Supplier Part Number 1=541-10.0LCT-ND, TempCo="100 ppm/C", Tolerance_%=1%, Value2=0.063W, Value_Code=10R0, ValueDisplayed=10.0
R6: library part CMP-0017851-1, "RES, 10.0, 1%, 0.25 W, 1206", Manufacturer="Yageo America", Power_W=250mW, Supplier Part Number 1=311-10.0FRCT-ND, TempCo="200 ppm/C", Tolerance_%=1%, Value2=0.25W, Value_Code=10R0, ValueDisplayed=10.0
R7 R8: library part CMP-0026750-1, "RES, 3.30 k, 1%, 0.063 W, AEC-Q200 Grade 0, 0402", Manufacturer="KOA Speer", Power_W=63mW, Supplier Part Number 1=660-RK73H1ETTP3301F, TempCo="100 ppm/C", Tolerance_%=1%, Value2=0.063W, Value_Code=3k30, ValueDisplayed=3.30k
R12: library part CMP-0025830-4, "RES, 5.1 k, 5%, 0.1 W, AEC-Q200 Grade 0, 0603", Manufacturer=Vishay-Dale, Power_W=100mW, Supplier Part Number 1=541-5.1KGCT-ND, TempCo="200 ppm/C", Tolerance_%=5%, Value2=0.1W, Value_Code=5k10, ValueDisplayed=5.1k
R14: library part CMP-0016557-2, "RES, 0.01, 1%, 1 W, 2010", Manufacturer=Vishay-Dale, Power_W=1W, Supplier Part Number 1=WSLF-.01CT-ND, TempCo="75 ppm/C", Tolerance_%=1%, Value_Code=R010, ValueDisplayed=0.01
R40: library part CMP-0026994-4, "RES, 10 k, 5%, 0.1 W, AEC-Q200 Grade 0, 0402", Manufacturer=Panasonic, Power_W=100mW, Supplier Part Number 1=P10KJCT-ND, TempCo="200 ppm/C", Tolerance_%=5%, Value2=0.1W, Value_Code=10k0, ValueDisplayed=10k
RT2: library part CMP-0084566-1, "Thermistor, DEC0002A (X1SON-2)", Alternate Manufacturer="Texas Instruments", Alternate PartNumber=TMP6131DECT
U1: library part CMP-0088771-1, "Automotive Dual USB Type-C Power Delivery Controller with Buck-Boost Regulator", Manufacturer="Texas Instruments", Max Supply Voltage=18V, Min Supply Voltage=4.5V, Nominal Supply Current=2-60mA, Operating Temperature Range="-40°C to +150°C", Output Voltage=3-21V, Switching Frequency=300/400/450kHz
U2: library part CMP-0005262-2, "256K I2C CMOS Serial EEPROM, TSSOP-8", Manufacturer=Microchip, Supplier Part Number 1=24LC256-I/ST-ND

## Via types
v1: diameter 0.762, hole 0.381, Component Side to Solder Side, 234 vias
v2: diameter 0.305, hole 0.152, Component Side to Solder Side, 135 vias
v3: diameter 0.305, hole 0.203, Component Side to Solder Side, 21 vias
v4: diameter 0.406, hole 0.203, Component Side to Solder Side, 10 vias
v5: diameter 0.381, hole 0.254, Component Side to Solder Side, tented both sides, 9 vias
v6: diameter 0.635, hole 0.381, Component Side to Solder Side, 7 vias
v7: diameter 0.508, hole 0.254, Component Side to Solder Side, 3 vias
v8: diameter 0.508/0.508/0.508/0.508 (per signal layer), hole 0.254, Component Side to Solder Side, 1 vias
v9: diameter 0.406, hole 0.254, Component Side to Solder Side, 1 vias

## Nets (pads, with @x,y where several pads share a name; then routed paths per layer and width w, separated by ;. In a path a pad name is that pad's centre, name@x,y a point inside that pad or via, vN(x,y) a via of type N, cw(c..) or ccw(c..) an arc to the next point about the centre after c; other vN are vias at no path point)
AGND: C1.1 C2.2 C3.1 C7.1 C10.2 C12.2 C13.2 C14.2 C15.2 C16.2 C17.1 C18.1 C19.1 C20.1 C21.2 C22.1 C24.2 C25.1 C26.1 C27.2 C29.2 C30.2 C32.2 C33.2 C35.2 C36.2 C37.2 C39.2 C40.2 C41.2 C44.2 C45.2 C46.2 C50.1 C51.1 C68.2 Designator21.0 I2C.1 J10.1 J10.2 J10.3 J10.4 J10.A1 J10.A12 J10.B1 J10.B12 L4.2 R1.1 R2.1 R6.1 R12.1 RT2.1 U1.5 U1.13 U2.1 U2.2 U2.3 U2.4 U2.7 | length 6.7
  Component Side w0.254: U1.5@12.243,37.182 13.433,37.182 v3@13.437,37.186 ; v3(13.411,37.186) v3@13.437,37.186 ; C36.2@13.995,37.186 C36.2@13.945,37.186 v3@13.437,37.186 ; C15.2@14.606,36.524 C15.2@15.088,36.524
  Solder Side w0.254: C7.1@16.789,36.525 17.018,36.297 17.069,36.297 17.247,36.119 17.247,35.687 18.547,34.386 U2.7@18.547,33.32 ; U2.1@17.882,38.633 U2.1@17.882,39.065
  other v1: 0.152,18.491 21.336,19.025 22.403,19.025 24.46,19.279 23.546,19.329 -0.813,19.355 -1.702,19.38 0.178,19.38 21.361,19.837 22.403,19.888 -0.762,20.32 -1.651,20.366 23.571,20.447 24.409,20.447 -0.787,21.463 -1.651,21.478 23.597,21.59 24.409,21.59 21.158,22.225 -0.813,22.53 -1.651,22.591 23.571,22.733 24.409,22.733 21.133,23.089 7.747,23.546 8.862,23.546 9.977,23.546 11.091,23.546 12.206,23.546 13.321,23.546 16.665,23.546 17.78,23.546 -0.762,23.647 -1.651,23.703 23.546,23.825 24.384,23.83 21.133,24.054 16.612,24.486 17.755,24.486 11.252,24.613 12.217,24.638 13.31,24.689 -1.651,24.816 -0.711,24.816 23.546,24.943 24.384,24.943 21.107,24.968 11.278,25.73 12.217,25.756 13.31,25.756 0.635,25.883 -0.457,25.908 -1.651,25.928 21.184,26.01 22.276,26.055 24.384,26.055 23.241,26.081 7.671,26.975 8.786,26.975 9.9,26.975 11.015,26.975 12.13,26.975 13.245,26.975 14.359,26.975 15.474,26.975 16.589,26.975 17.704,26.975 -0.483,26.99 -1.651,27.041 0.66,27.041 21.158,27.051 22.276,27.168 24.384,27.168 23.241,27.193 7.671,28.016 8.814,28.016 13.259,28.016 11.024,28.042 12.141,28.042 9.906,28.067 -0.483,28.103 -1.651,28.153 0.66,28.153 22.276,28.28 24.384,28.28 23.241,28.306 -0.483,29.215 -1.651,29.266 0.66,29.266 22.276,29.393 24.384,29.393 23.241,29.418 -0.483,30.328 -1.651,30.378 0.66,30.378 22.276,30.505 24.384,30.505 23.241,30.531 -0.483,31.293 -1.651,31.344 0.66,31.344 22.276,31.547 24.384,31.547 23.241,31.572 2.87,32.156 1.473,32.207 1.499,33.172 2.845,33.172 1.499,34.265 2.87,34.315 15.24,40.97 4.521,41.681 3.632,41.707 15.24,41.758 22.25,44.374 23.495,44.374 24.765,44.425 -1.803,44.602 -0.61,44.602 0.711,44.628 22.25,45.486 23.495,45.486 24.765,45.537 -1.803,45.715 -0.61,45.715 0.711,45.74 22.25,46.599 23.495,46.599 24.765,46.65 -1.803,46.827 -0.61,46.827 0.711,46.853 22.25,47.711 23.495,47.711 24.765,47.762 -1.803,47.94 -0.61,47.94 0.711,47.965 22.25,48.824 23.495,48.824 24.765,48.875 -1.803,49.052 -0.61,49.052 0.711,49.078 22.25,49.936 23.495,49.936 24.765,49.987 -1.803,50.165 -0.61,50.165 0.711,50.19 23.825,51.079 24.765,51.1 -1.803,51.278 -0.914,51.283 17.348,51.435 16.231,51.46 23.851,52.172 24.765,52.212 -1.803,52.39 -0.889,52.426 16.231,52.553 17.348,52.603 23.876,53.289 24.765,53.325 -1.803,53.503 -0.838,53.492 16.205,53.721 17.348,53.746 23.851,54.407 24.765,54.437 -0.838,54.61 -1.778,54.635 16.154,54.839 17.348,54.864 23.825,55.474 24.765,55.55 -1.778,55.716 -0.838,55.728 16.154,55.982 17.348,56.058 0.686,56.363 22.301,56.363 23.851,56.464 24.765,56.49 -1.778,56.818 -0.584,56.818 16.129,57.099 14.935,57.125 17.323,57.125 13.691,57.15 12.344,57.175 22.327,57.201 0.711,57.252 11.252,57.353 23.495,57.52 24.765,57.571 -1.778,57.919 -0.584,57.919 22.301,58.039 0.711,58.166 10.465,58.166 23.495,58.621 24.765,58.672 7.01,58.877 22.276,58.877 5.817,58.903 8.23,58.903 4.902,58.928 9.55,58.928 -1.778,59.02 -0.584,59.02 0.737,59.046 22.25,59.723 23.495,59.723 24.765,59.773 4.902,59.944 -1.778,60.122 -0.584,60.122 0.737,60.147 22.25,60.824 23.495,60.824 24.765,60.875 4.851,60.985 -1.727,61.163 -0.533,61.163 0.787,61.189 22.25,61.925 23.495,61.925 24.765,61.976 15.697,62.001 18.212,62.001 19.431,62.001 16.942,62.027
  other v2: 9.068,28.956 9.398,28.956 9.754,28.956 10.109,28.956 10.49,28.956 10.82,28.956 11.176,28.956 10.109,29.312 9.068,29.337 9.398,29.337 9.754,29.337 10.49,29.337 10.82,29.337 11.151,29.337 9.068,31.471 9.398,31.471 9.728,31.471 10.058,31.471 10.389,31.471 10.719,31.471 11.074,31.471 9.601,32.944 9.982,32.944 10.389,32.944 10.744,32.944 9.246,32.969 9.55,33.858 9.982,33.858 10.363,33.858 9.957,35.001 14.072,35.738 14.453,35.738 14.834,35.738 15.215,35.738 9.957,35.865 9.957,36.83 16.18,37.262 16.535,37.262 16.916,37.262 17.272,37.262 16.18,37.617 16.535,37.617 16.891,37.617 17.247,37.617 9.957,37.694 9.982,38.608 16.053,39.345 16.053,39.726 9.957,39.853 16.053,40.056 9.957,40.183 16.053,40.386 9.957,40.513 16.053,40.716 9.804,40.869 10.135,40.869 16.053,41.072 9.627,41.173 9.982,41.173 10.312,41.173 16.053,41.427 16.053,41.834 16.434,41.834 16.789,41.834 17.145,41.834 17.501,41.834 17.882,41.834
  other v3: 6.858,61.925 7.341,61.925 7.899,61.925 5.817,61.951 6.35,61.951 6.858,62.459 7.341,62.459 7.874,62.459 5.817,62.484 6.325,62.484
  other v4: 6.223,34.722 5.74,35.306 6.223,35.306 5.766,35.89 6.223,35.89
  other v5: 7.087,19.812 7.645,19.812 8.204,19.812 5.918,19.837 6.502,19.837 5.334,20.98 5.842,20.98 5.334,21.463 5.842,21.463
  other v6: 9.957,41.808 9.957,42.875 5.69,69.85 8.541,69.85 11.392,69.85 14.243,69.85 17.094,69.85
BATGND: C28.2 C34.2 J1.2 L4.1
BOOT1: C5.1 U1.16 | length 2.7
  Component Side w0.254: C5.1@6.934,40.945 6.934,40.767 7.366,40.335 8.153,40.335 8.458,40.03 U1.16@8.458,39.319
BOOT2: C6.1 U1.10 | length 2.5
  Component Side w0.152: U1.10@11.468,39.257 U1.10@11.497,39.285
  Component Side w0.254: U1.10@11.468,39.257 11.468,39.713 12.065,40.31 12.395,40.31 12.878,40.792 C6.1@12.878,40.894 ; C6.1@12.852,40.919 C6.1@12.878,40.894 ; C6.1@12.878,40.919 C6.1@12.878,40.894
EN_UVLO: R3.1 U1.6 | length 6.3
  Component Side w0.178: U1.6@11.887,37.682 U1.6@12.243,37.682 12.255,37.694 v3(13.411,37.694) ; v4(13.64,34.925) R3.1@14.754,34.925
  Signal Layer 2 w0.178: v3(13.411,37.694) 13.233,37.694 12.954,37.414 12.954,35.128 13.132,34.95 v4@13.64,34.95
I2C1_SCL: I2C.2 R7.1 U1.3 U2.6 | length 44.5
  Component Side w0.178: U1.3@12.243,36.182 12.255,36.17 v3(13.437,36.17)
  Signal Layer 2 w0.178: v3(13.437,36.17) 17.475,36.17 17.932,35.712 v4(17.932,35.662) 18.644,35.662 21.031,38.049 21.031,65.303 I2C.2@19.126,67.208
  Solder Side w0.178: v4(17.932,35.662) 19.202,34.392 U2.6@19.202,33.782 ; R7.1@18.491,31.445 18.491,31.648 19.197,32.354 U2.6@19.197,33.32
I2C1_SDA: I2C.3 R8.1 U1.4 U2.5 | length 41.3
  Component Side w0.178: U1.4@12.243,36.682 12.247,36.678 v3(13.411,36.678)
  Signal Layer 2 w0.178: v3(13.411,36.678) 17.747,36.678 17.751,36.682 v4(17.983,36.449) 18.542,36.449 20.422,38.329 20.422,63.373 I2C.3@19.202,64.592
  Solder Side w0.178: v4(17.983,36.449) 19.837,34.595 U2.5@19.837,33.782 ; U2.5@19.847,33.32 19.847,31.308 R8.1@19.888,31.267
IN: C1.2 C3.2 C21.1 C25.2 C26.2 C27.1 C37.1 L5.2 R3.2 U1.15 | length 10.9
  Component Side w0.178: v3(16.002,34.163) 16.002,34.413 16.434,34.845 R3.2@16.354,34.925
  Signal Layer 2 w0.254: v3(8.255,30.836) 14.097,30.836 16.002,32.741 v3@16.002,34.138
  Solder Side w0.254: v3@15.951,34.163 v3@15.977,34.188
  other v2: 2.819,23.266 3.175,23.266 2.464,23.292 3.531,23.292 3.886,23.292 4.242,23.292 4.623,23.317 4.978,23.317 5.334,23.317 5.69,23.317 6.02,23.317 2.819,23.622 3.175,23.622 3.531,23.622 2.464,23.647 3.886,23.647 4.242,23.647 4.623,23.647 4.978,23.647 5.334,23.647 5.69,23.673 6.02,23.673 2.464,24.003 2.819,24.003 3.175,24.003 3.531,24.003 3.886,24.003 4.242,24.003 4.623,24.003 4.978,24.003 5.334,24.003 5.69,24.003 6.02,24.003 2.464,24.359 2.819,24.359 3.175,24.359 3.531,24.359 3.886,24.359 4.242,24.359 4.597,24.359 4.978,24.359 5.334,24.359 5.69,24.359 6.02,24.359 6.833,31.674 5.893,31.699 6.375,31.699 7.01,31.979 6.121,32.004 6.579,32.004 6.807,32.334 6.375,32.36 7.036,32.639 6.655,32.69 7.696,32.969 6.909,32.995 7.29,32.995 7.087,33.274 7.493,33.274 7.899,33.274
  other v7: 8.941,40.043
  other v8: 8.915,33.909
IRQ1: U1.2
LDO_1V5: C15.1 C36.1 U1.7 | length 3
  Component Side w0.254: U1.7@12.243,38.182 13.899,38.182 C36.1@13.945,38.227 ; C36.1@13.945,38.186 15.122,38.186 C15.1@15.164,38.227
LDO_3V3: C7.2 C12.1 C33.1 R7.2 R8.2 R40.2 U1.27 U2.8 | length 33.1
  Component Side w0.254: C12.1@5.131,32.639 5.207,32.639 C33.1@6.223,33.655 6.35,33.782 6.858,33.782 v3(6.883,33.807) 7.264,33.807 7.442,33.985 8.255,33.985 8.468,34.198 U1.27@8.468,34.607 ; v4(13.665,40.132) R40.2@14.334,40.132
  Signal Layer 2 w0.254: v3@6.934,33.807 8.103,33.807 8.585,33.325 8.585,32.944 9.068,32.461 13.513,32.461 15.748,34.696 v9(17.526,34.696) ; 12.128,32.474 12.522,32.868 12.522,38.989 v4(13.665,40.132)
  Solder Side w0.254: C7.2@16.637,35.72 16.637,35.636 17.526,34.747 v9(17.526,34.696) ; v9@17.577,34.696 v9(17.526,34.696) ; U2.8@17.882,33.757 17.882,34.341 v9(17.526,34.696) ; U2.8@17.907,33.096 17.907,30.378 18.228,30.058 R7.2@18.517,30.058 ; R7.2@18.517,30.048 18.552,30.083 R8.2@19.914,30.083
LDO_5V: C13.1 C14.1 U1.21 | length 4.4
  Component Side w0.254: C14.1@4.597,38.602 4.597,37.881 4.666,37.813 4.666,37.389 5.588,37.389 5.795,37.182 U1.21@7.693,37.182
NetC4_2: C4.2 R1.2 | length 2
  Component Side w0.254: R1.2@2.718,45.822 R1.2@2.845,45.949
  Component Side w0.762: C4.2@2.819,47.739 2.845,47.714 R1.2@2.845,45.949
NetC8_2: C8.2 R2.2 | length 1.9
  Component Side w0.254: R2.2@16.561,45.999 R2.2@16.713,45.847
  Component Side w0.762: R2.2@16.561,45.999 C8.2@16.561,47.701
